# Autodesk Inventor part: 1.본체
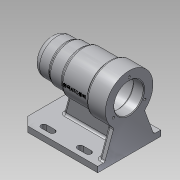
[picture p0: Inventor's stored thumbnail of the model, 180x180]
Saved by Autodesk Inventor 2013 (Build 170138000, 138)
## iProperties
Created: 2017-09
Part Number: 1.본체
Material: 알루미늄 6061
Document SubType Name: Modeling
Designer: Administrator
Density: 2.40731 g/cm^3
Mass: 620.105 g
Surface Area: 709.374 cm^2
Volume: 257.592 cm^3
Author: Administrator
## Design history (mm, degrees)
sketch "스케치1"
  geometry: L1 (56, -45)-(-44, -45); L2 (-56, -33)-(-56, 33); L3 (-44, 45)-(56, 45); L4 (56, 45)-(56, -45); L5 (56, -45)-(-56, 45); L6 (-56, -45)-(56, 45); L7 (-56, 33)-(-44, 45); L8 (-44, -45)-(-56, -33); 1 further point
  constraints: 16 end point, 4 point on line, 2 midpoint, 2 parallel, 1 horizontal, 1 perpendicular
  dimensions: "d0" = 112 distance of L5.end L3.end; "d2" = 90 distance of L3.end L1.start; "d3" = 12 distance of L2.end L5.end; "d4" = 12 distance of L3.start L5.end (= d3); "d5" = 12 distance of L1.end L6.start (= d3); "d6" = 12 distance of L2.start L6.start (= d5)
extrude "돌출1" new body sketch "스케치1" distance "d7" = 8; taper "d8" = 0 deg
sketch "스케치2"
  geometry: L1 (-56, 70)-(56, 70); L2 (44, 0)-(-56, 0) reference; L3 (56, 70)-(56, 95); L4 (56, 95)-(31, 95); L5 (31, 95)-(31, 97); L6 (31, 97)-(11, 97); L7 (11, 97)-(11, 100); L8 (11, 100)-(-28, 100); L9 (-28, 100)-(-28, 104); L10 (-28, 104)-(-56, 104); L11 (-56, 104)-(-56, 70); L12 (-56, 0)-(-56, 8) reference; L13 (56, 0)-(44, 0) reference; 2 further points
  constraints: 20 end point, 7 parallel, 2 perpendicular, 1 horizontal, 1 midpoint, 1 point on line
  dimensions: "d9" = 70 distance from line of L1.start L2; "d10" = 112 distance of L1.start L1.end; "d11" = 25 distance of L3.end L4.end; "d12" = 45 distance between parallel lines of L7 L3; "d13" = 84 distance between parallel lines of L9 L3; "d14" = 50 diameter of L4 L1; "d15" = 54 diameter of L6 L1; "d16" = 60 diameter of L8 L1; "d17" = 68 diameter of L10 L1
revolve "회전1" sketch "스케치2" stored, may be unused: angle "d18" = 90 deg
sketch "스케치3"
  geometry: L1 (-56, 36)-(-56, 104) reference; L2 (56, 45)-(56, 95) reference; L3 (56, 70)-(-56, 70); L4 (-56, 91)-(-41, 91); L5 (-41, 91)-(-41, 91); L6 (-38, 94)-(10, 94); L7 (13, 91)-(13, 91); L8 (13, 91)-(24.7, 91); L9 (25, 90.7)-(25, 87.5); L10 (25, 87.5)-(42.7, 87.5); L11 (43, 87.2)-(43, 86); L12 (43, 86)-(46.7, 86); L13 (47, 85.7)-(47, 80.5); L14 (47, 80.5)-(47, 80.5); L15 (50, 77.5)-(50, 70); A1 r 3 centre (47, 77.5) between (50, 77.5) and (47, 80.5); A2 r 0.3 centre (46.7, 85.7) between (47, 85.7) and (46.7, 86); A3 r 0.3 centre (42.7, 87.2) between (43, 87.2) and (42.7, 87.5); A4 r 0.3 centre (24.7, 90.7) between (25, 90.7) and (24.7, 91); A5 r 3 centre (10, 91) between (13, 91) and (10, 94); A6 r 3 centre (-38, 91) between (-38, 94) and (-41, 91); 7 further points
  constraints: 26 end point, 14 point on line, 12 point on circle, 12 tangent, 10 parallel, 6 centre point, 2 collinear, 2 equal radius, 2 midpoint, 1 perpendicular
  dimensions: "d19" = 42 diameter of L4 L3; "d21" = 48 diameter of L6 L3; "d22" = 54 distance of point (-41, 94) point (13, 94); "d23" = 15 distance of L4.start L4.end; "d24" = 12 distance of L7.end point (25, 91); "d25" = 18 distance of L9.end point (43, 87.5); "d26" = 4 distance of L11.end point (47, 86); "d27" = 3 distance of L13.end point (50, 80.5); "d28" = 21 diameter of L14 L3; "d29" = 32 diameter of L12 L3; "d30" = 35 diameter of L10 L3; "d31" = 3 radius of A1; "d32" = 0.3 radius of A2; "d33" = 3 radius of A5; "d34" = 3 radius of A6
revolve "회전2" sketch "스케치3" stored, may be unused: angle "d35" = 90 deg
chamfer "모따기1" distance "d36" = 1; stored, may be unused: second distance "d37" = 2, angle "d38" = 45 deg
sketch "스케치5"
  geometry: L1 (0, 90)-(-8, 90) reference; L2 (-8, 0)-(-8, 90) reference; L3 (0, 0)-(-8, 0) reference; L4 (-43.992, 23.1)-(-8, 10); L5 (-43.992, 66.9)-(-8, 80); A1 r 34 centre (-70, 45) between (-43.992, 23.1) and (-43.992, 66.9) reference; 1 further point
  constraints: 4 end point, 2 point on circle, 2 point on line
  dimensions: "d41" = 10 distance from line of L4.end L3; "d42" = 10 distance from line of L5.end L1; "d43" = 110 deg angle of L4 L2; "d44" = 110 deg angle of L5 L2
extrude "돌출2" join sketch "스케치5" distance "d45" = 8; taper "d46" = 0 deg
sketch "스케치6"
  geometry: L1 (44, 8)-(-56, 8) reference; L2 (56, 0)-(56, 8) reference; L3 (56, 8)-(44, 8) reference; L4 (-48, 8)-(-48, 43.992) reference; L5 (-48, 36)-(-28, 36) reference; L6 (-28, 40)-(11, 40) reference; L7 (-28, 36)-(-28, 104) reference; L8 (11, 40)-(11, 100) reference; L9 (11, 43)-(31, 43) reference; L10 (31, 45)-(31, 95) reference; L11 (24.622, 43)-(34, 8); 1 further point
  constraints: 2 end point, 2 point on line
  dimensions: "d47" = 105 deg angle of L11 L1; "d48" = 22 distance from line of L2 L11.end
feature "리브1" sketch "스케치6" dims "d49" = 1, "d50" = 8, "d51" = 0, "d52" = 0, "d53" = 1, "d54" = 1
sketch "스케치7"
  geometry: L1 (56, -45)-(56, -35) reference; L2 (48, -35)-(48, -4) reference; L3 (-20, -34)-(20, -34); L4 (20, -30)-(32, -30); L5 (32, -38)-(20, -38); L6 (-20, -38)-(-32, -38); L7 (-32, -30)-(-20, -30); A1 r 4 centre (20, -34) between (20, -30) and (20, -38); A2 r 4 centre (32, -34) between (32, -30) and (32, -38); A3 r 4 centre (-32, -34) between (-32, -30) and (-32, -38); A4 r 4 centre (-20, -34) between (-20, -30) and (-20, -38); 1 further point
  constraints: 10 end point, 8 point on circle, 5 tangent, 4 centre point, 3 parallel, 2 coincident, 2 horizontal alignment, 1 perpendicular
  dimensions: "d55" = 40 distance of L3.start L3.end; "d57" = 34 distance from line of point (0, 0) L3; "d59" = 12 distance of A2.centre A1.centre; "d60" = 8 diameter of A1; "d61" = 8 diameter of A2; "d62" = 12 distance of A4.centre A3.centre; "d63" = 8 diameter of A3; "d64" = 8 diameter of A4; "d67" = 24 distance from line of A2.centre L1
extrude "돌출3" cut sketch "스케치7" stored distance "d65" = 8; taper "d66" = 0 deg
sketch "스케치8"
  geometry: A1 r 34 centre (-70, 45) between (-43.992, 66.9) and (-43.992, 23.1) reference; 2 further points
  constraints: 1 horizontal alignment
  dimensions: "d68" = 26 distance of point (-96, 45) A1.centre
hole "구멍1" sketch "스케치8" at (-96, 45) diameter "d69" = 3.242; stored, may be unused: countersink angle "d73" = 90 deg, drill point angle "d75" = 118 deg; dims "d70" = 8, "d71" = 4, "d72" = 2, "d74" = 11
fillet "모깎기1" dims "d79" = 9
fillet "모깎기2" dims "d80" = 3
fillet "모깎기3" dims "d81" = 3
fillet "모깎기4" dims "d82" = 3
fillet "모깎기6" dims "d84" = 3
fillet "모깎기7" dims "d85" = 2
fillet "모깎기8" dims "d86" = 3
fillet "모깎기9" dims "d87" = 3
fillet "모깎기10" dims "d88" = 3
node "작업 평면1"
sketch "스케치9"
  geometry: L1 (56, 104)-(56, 45.289) reference; L2 (56, 0)-(-44, 0) reference; 3 further points
  constraints: 1 other
  dimensions: "d90" = 48 distance from line of point (8, 70) L1; "d91" = 70 distance from line of point (8, 70) L2
feature "엠보싱1" sketch "스케치9" dims "d0" = 112, "d2" = 90, "d3" = 12, "d4" = 12 (= d3), "d5" = 12 (= d3), "d6" = 12 (= d5), "d92" = 0.5, "d93" = 0
node "솔리드1"
mirror "대칭1"
pattern_circular "원형 패턴1" dims angle "d77" = 360 deg
other parameters: "d89" = -54
